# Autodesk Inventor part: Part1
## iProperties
Shininess: 64.0
Length Units: 11269
Angle Units: 11279
Time Units: 11290
Mass Units: 11283
Length Display Precision: 3
Angle Display Precision: 2
Compacted: True
Part Number: Part1
Document SubType Name: Modeling
Created: 2002-12
Designer: deepak
Density: 0.0
Volumn: 0.0
Area: 0.0
PropertySet Name: Model Information
Control State: 0
Master: False
Checked Out: False
Author: deepak
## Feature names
1. Extrusion1
